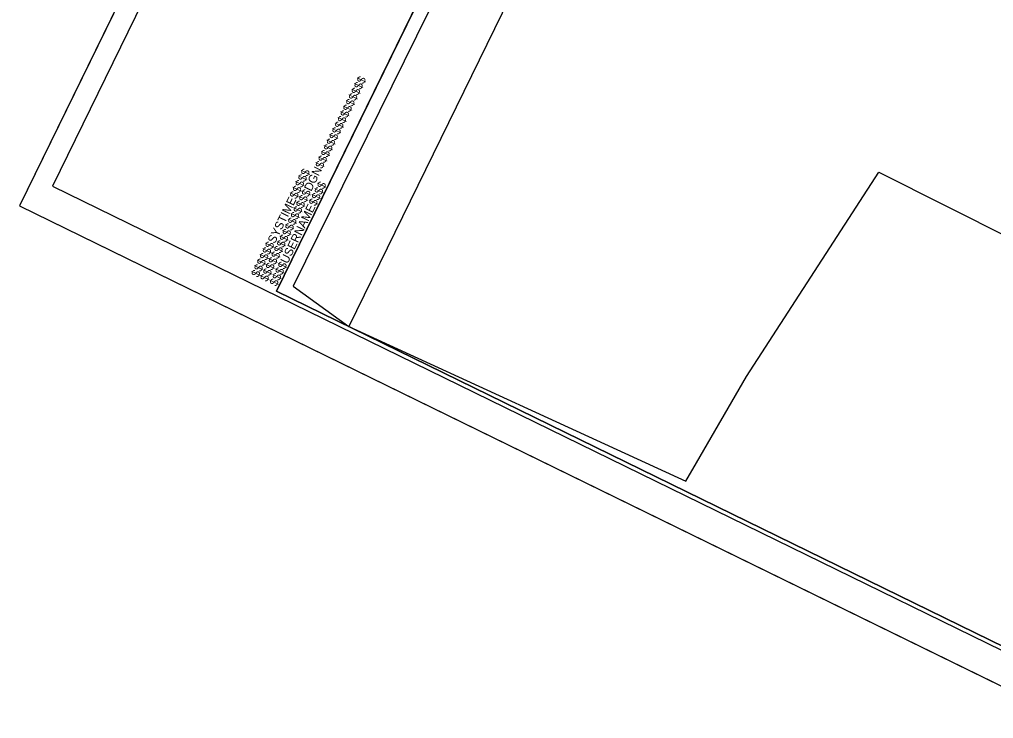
# Model space of a CAD drawing. Extents: x 1519210 to 1521378, y 637447 to 639183.
# Drawn here: x 1519210 to 1519814, y 637881 to 638315 of the extents above; entities that cross this region are included whole.
import ezdxf

# ---------------------------------------------------------------- set-up
doc = ezdxf.new("R2010")
doc.units = 0
for name, color, linetype in [('Sheet Clip Boundary CELL', 7, 'Continuous'), ('Sheet Cutting Line CELL', 7, 'Continuous'), ('Sheet Layout Plan Border', 7, 'Continuous'), ('Sheet Plan CELL', 7, 'Continuous'), ('Sheet Plan Layout CELL', 7, 'Continuous'), ('Sheet Plot Border Inside CELL', 7, 'Continuous'), ('Sheet Plot Border Outside CELL', 7, 'Continuous')]:
    doc.layers.add(name, color=color, linetype=linetype)

msp = doc.modelspace()

# ---------------------------------------------------------------- linework, layer by layer
at = {"layer": 'Sheet Clip Boundary CELL'}
msp.add_lwpolyline([(1520331.06, 638791.96), (1519849.49, 639022.82), (1519814.87, 639040.3), (1519565, 638526.58), (1519563.19, 638522.26), (1519560.59, 638515.62), (1519559.85, 638511.52), (1519555.69, 638506.23), (1519379.66, 638149.4), (1519414.26, 638124.36), (1519623.39, 638028.38), (1519630.01, 638039.72), (1519661.19, 638093.36), (1519743.2, 638220.14), (1520032.2, 638075.03), (1519956.23, 637866.66), (1520671.92, 637509.27)], dxfattribs=at)
at = {"layer": 'Sheet Cutting Line CELL'}
for p, q in [((1519690.98, 639182.91), (1519209.9, 638199.25)), ((1519209.9, 638199.25), (1520722.21, 637459.61))]:
    msp.add_line(p, q, dxfattribs=at)
at = {"layer": 'Sheet Layout Plan Border'}
msp.add_lwpolyline([(1519414.26, 638124.36), (1520671.92, 637509.27), (1521040.32, 638262.52), (1520870.3, 638345.67), (1520963.21, 638535.65), (1519875.58, 639067.59)], close=True, dxfattribs=at)
at = {"layer": 'Sheet Plan CELL'}
msp.add_line((1519369.35, 638146.33), (1519369.35, 638146.33), dxfattribs=at)
for points in [[(1521178.17, 638430.52), (1519830.66, 639089.56), (1519369.35, 638146.33), (1520716.83, 637487.3)], [(1519369.35, 638146.33), (1519830.63, 639089.55), (1520998.45, 638518.44), (1520906.34, 638330.09), (1521086.04, 638242.2), (1520716.83, 637487.3)]]:
    msp.add_lwpolyline(points, close=True, dxfattribs=at)
at = {"layer": 'Sheet Plan Layout CELL'}
msp.add_lwpolyline([(1519830.63, 639089.55), (1519369.35, 638146.33), (1520716.82, 637487.31), (1521085.22, 638240.56), (1520870.3, 638345.67), (1520963.21, 638535.65)], close=True, dxfattribs=at)
at = {"layer": 'Sheet Plot Border Inside CELL'}
msp.add_lwpolyline([(1519230.36, 638211.5), (1520726.95, 637479.57), (1521190.47, 638427.28), (1519693.87, 639159.23)], close=True, dxfattribs=at)
at = {"layer": 'Sheet Plot Border Outside CELL'}
msp.add_lwpolyline([(1519209.9, 638199.25), (1520722.21, 637459.61), (1521203.3, 638443.27), (1519690.98, 639182.91)], close=True, dxfattribs=at)

# ---------------------------------------------------------------- texts
at = {"layer": 'Sheet Plan CELL'}
for s, p in [('$$$$$$$$$$$$$$$$DGN$$$$$$$$$$$$$$$$', (1519363.52, 638151.81)), ('$$$$$$SYSTIME$$$$$', (1519358.06, 638154.45)), ('$$$$USERNAME$$$$', (1519369.41, 638148.94))]:
    msp.add_text(s, height=5.25, rotation=63.93773, dxfattribs=at).set_placement(p)

doc.saveas('drawing.dxf')
